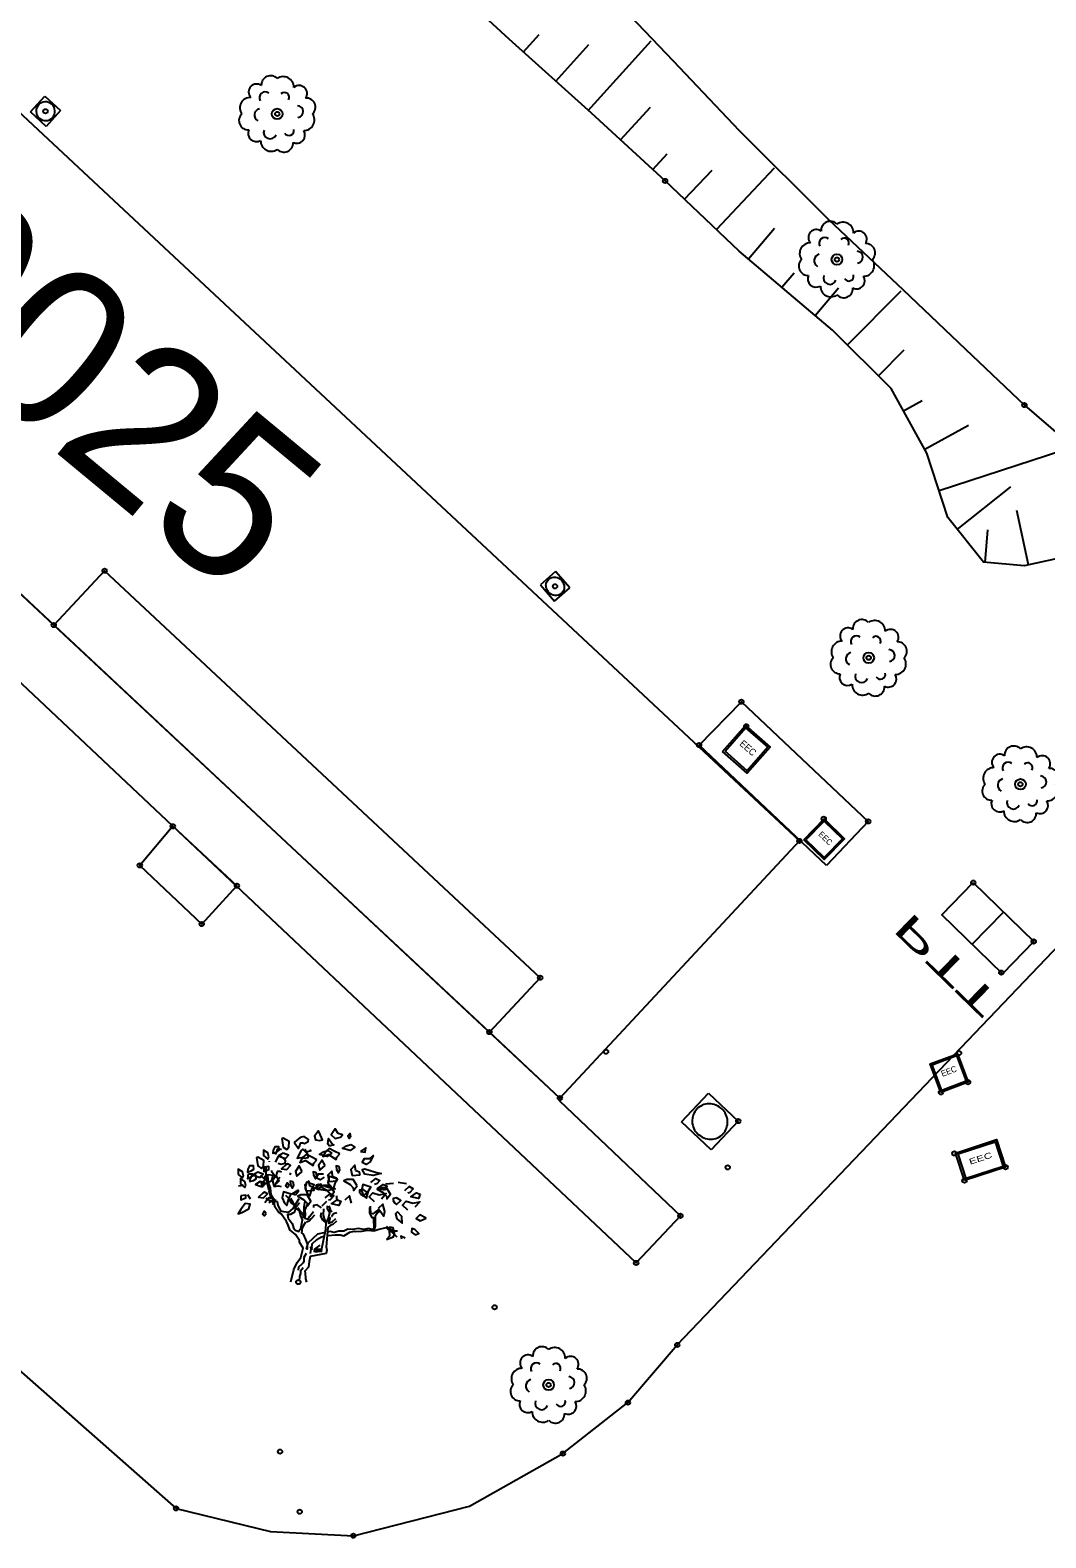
# Model space of a CAD drawing. Extents: x 344013 to 344423, y 298505 to 298795.
# Drawn here: x 344153.42 to 344176.66, y 298671.56 to 298706.06 of the extents above; entities that cross this region are included whole.
import ezdxf

# ---------------------------------------------------------------- set-up
doc = ezdxf.new("R2010")
doc.units = 0
for name, color, linetype in [('Default', 7, 'Continuous'), ('DH_CADRE -CARTOUCHE', 7, 'Continuous'), ('DH_CADRE-CARTOUCHE-NORD', 7, 'Continuous'), ('GO MUR EXTERIEUR', 7, 'Continuous'), ('PC_CONCRETE', 7, 'Continuous'), ('PS_BOLT', 7, 'Continuous'), ('PS_CONST', 7, 'Continuous'), ('PS_HIDDEN', 7, 'Continuous'), ('RES_ELECTRICITE', 7, 'Continuous'), ('TOPO_POINT', 7, 'Continuous'), ('TOPO_TALUS-TERRAIN NATUREL', 7, 'Continuous'), ('VOIRIE_BORDURE', 7, 'Continuous'), ('VOIRIE_ESPACE VERT', 7, 'Continuous')]:
    doc.layers.add(name, color=color, linetype=linetype)

# ---------------------------------------------------------------- blocks, each defined once
blk = doc.blocks.new('CT2')
at = {"layer": 'Default'}
blk.add_lwpolyline([(0, 0), (1, 0), (1, 1), (0, 1)], close=True, dxfattribs=at)
blk.add_lwpolyline([(0.5, 1), (0.5, 0)], dxfattribs=at)
blk.add_text('PTT', height=0.6, dxfattribs=at).set_placement((-0.3, 1.425))
blk = doc.blocks.new('REG_INC')
at = {"layer": 'Default'}
for p, q in [((0, 1), (1, 1)), ((0, 0), (0, 1)), ((1, 1), (1, 0)), ((1, 0), (0, 0))]:
    blk.add_line(p, q, dxfattribs=at)
for centre, start, end in [((0.498, 0.5), 135.0055, 180.0055), ((0.5, 0.498), 90.0058, 135.0058), ((0.5, 0.5), 45.0069, 90.0069), ((0.499, 0.499), 0.0066, 45.0066), ((0.501, 0.5), 180.0066, 225.0066), ((0.501, 0.499), 315.0055, 0.0055), ((0.499, 0.498), 225.0069, 270.0069), ((0.499, 0.5), 270.0058, 315.0058)]:
    blk.add_arc(centre, 0.44, start, end, dxfattribs=at)
blk = doc.blocks.new('RES_ELECTRICITE')
at = {"layer": 'RES_ELECTRICITE'}
for points in [[(0, 0), (0, 1), (1, 1), (1, 0)], [(0.05, 0.05), (0.05, 0.95), (0.95, 0.95), (0.95, 0.05)]]:
    blk.add_lwpolyline(points, close=True, dxfattribs=at)
blk.add_text('EEC', height=0.2, dxfattribs=at).set_placement((0.237, 0.46))
blk = doc.blocks.new('POINT_DISPLAY')
at = {"layer": 'Default'}
blk.add_circle((0, 0), 0.05, dxfattribs=at)
blk = doc.blocks.new('ARB1')
at = {"layer": 'Default'}
blk.add_circle((0, 0), 0.122, dxfattribs=at)
for centre, radius, start, end in [((-0.153, 0.664), 0.211, 43.6925, 183.5969), ((0.139, 0.613), 0.241, 358.4583, 125.1928), ((-0.613, 0.139), 0.241, 88.4583, 215.1928), ((-0.471, 0.503), 0.183, 53.9554, 222.2066), ((-0.276, 0.37), 0.134, 52.4396, 209.5496), ((0.164, 0.38), 0.112, 330.5895, 133.7127), ((0.501, 0.468), 0.183, 325.1444, 131.0175), ((0.664, 0.153), 0.211, 313.6925, 93.5969), ((-0.373, -0.024), 0.149, 103.7092, 242.3465), ((0.458, 0.052), 0.137, 276.6214, 88.967), ((0.613, -0.139), 0.241, 268.4583, 35.1928), ((-0.664, -0.153), 0.211, 133.6925, 273.5969), ((-0.478, -0.443), 0.19, 155.2243, 300.9377), ((-0.139, -0.613), 0.241, 178.4583, 305.1928), ((-0.163, -0.42), 0.148, 159.5371, 338.1663), ((0.153, -0.664), 0.211, 223.6925, 3.5969), ((0.271, -0.38), 0.112, 210.5895, 13.7127), ((0.448, -0.483), 0.188, 243.1323, 33.0297)]:
    blk.add_arc(centre, radius, start, end, dxfattribs=at)
blk = doc.blocks.new('FLAMBOY')
at = {"layer": 'Default'}
for p, q in [((-0.832, 3.464), (-0.832, 3.442)), ((-0.238, 3.069), (-0.213, 3.132)), ((-1.57, 2.764), (-1.707, 2.742)), ((2.497, 2.813), (2.722, 2.832)), ((3.097, 2.813), (2.859, 2.854)), ((-1.371, 2.378), (-1.446, 2.497)), ((0.808, 2.303), (0.671, 2.171)), ((0.866, 1.688), (0.866, 1.688)), ((0.407, 0.927), (0.337, 1.011))]:
    blk.add_line(p, q, dxfattribs=at)
for points in [[(0.617, 4.053), (0.692, 4.072), (0.592, 4.288), (0.579, 4.328), (0.467, 4.172), (0.492, 4.072)], [(1.054, 4.113), (1.204, 4.15), (1.267, 4.213), (1.142, 4.25), (1.054, 4.388), (0.942, 4.213)], [(-0.471, 4.106), (-0.433, 3.866), (-0.333, 3.791), (-0.271, 3.866), (-0.258, 4.025), (-0.433, 4.122)], [(0.054, 4.141), (-0.108, 4.006), (-0.108, 3.985), (0.004, 3.825), (0.042, 3.906), (0.067, 3.985), (0.129, 3.985), (0.179, 3.966), (0.279, 4.025), (0.292, 4.085), (0.167, 4.163)], [(0.892, 3.891), (0.867, 3.95), (0.842, 3.95), (0.867, 4.106), (0.979, 3.95), (1.017, 3.928)], [(1.504, 3.938), (1.617, 3.863), (1.479, 3.763), (1.267, 3.822), (1.379, 3.9)], [(1.504, 4.15), (1.479, 4.25), (1.417, 4.172), (1.454, 4.113)], [(-1.195, 3.564), (-1.157, 3.324), (-1.057, 3.249), (-0.995, 3.324), (-0.982, 3.483), (-1.157, 3.58)], [(-0.846, 3.581), (-0.871, 3.697), (-0.996, 3.775), (-0.996, 3.622), (-0.871, 3.522)], [(-0.621, 3.722), (-0.546, 3.772), (-0.558, 3.872), (-0.671, 3.872), (-0.721, 3.772), (-0.733, 3.691)], [(-0.433, 3.691), (-0.571, 3.61), (-0.408, 3.55), (-0.358, 3.55), (-0.283, 3.631)], [(0.292, 3.644), (0.254, 3.685), (0.129, 3.803), (0.079, 3.763), (-0.008, 3.606), (-0.033, 3.547), (0.079, 3.569), (0.167, 3.547), (0.279, 3.569)], [(0.533, 3.5), (0.371, 3.581), (0.221, 3.656), (0.121, 3.562), (0.046, 3.421), (0.208, 3.481), (0.421, 3.34), (0.446, 3.403)], [(0.767, 3.338), (0.679, 3.494), (0.579, 3.338), (0.617, 3.2)], [(0.958, 3.693), (0.821, 3.593), (0.608, 3.653), (0.721, 3.731), (0.846, 3.768)], [(1.192, 3.669), (1.029, 3.75), (0.879, 3.825), (0.779, 3.731), (0.704, 3.591), (0.867, 3.65), (1.079, 3.51), (1.104, 3.572)], [(1.779, 3.738), (1.917, 3.716), (1.929, 3.838)], [(1.829, 3.422), (1.892, 3.541), (2.042, 3.541), (2.142, 3.622), (2.054, 3.441), (1.942, 3.366)], [(-1.72, 3.08), (-1.595, 2.98), (-1.57, 3.039), (-1.595, 3.155), (-1.72, 3.233)], [(-1.345, 3.18), (-1.27, 3.23), (-1.282, 3.33), (-1.395, 3.33), (-1.445, 3.23), (-1.457, 3.149)], [(-1.421, 3.103), (-1.308, 3.103), (-1.296, 3.038), (-1.446, 2.953)], [(-1.392, 2.878), (-1.279, 2.909), (-1.204, 2.959), (-1.217, 3.059), (-1.329, 3.059), (-1.379, 2.959)], [(-1.132, 3.008), (-1.082, 3.008), (-1.007, 3.089), (-1.157, 3.149), (-1.295, 3.067)], [(-0.958, 2.81), (-0.758, 2.906), (-0.721, 3.047), (-0.858, 3.066), (-0.983, 2.888), (-1.058, 2.772)], [(-0.983, 3.285), (-0.983, 3.166), (-0.846, 3.225), (-0.846, 3.306)], [(-0.7, 2.76), (-0.55, 2.897), (-0.638, 3.053), (-0.738, 2.897)], [(-0.308, 3.388), (-0.358, 3.36), (-0.483, 3.241), (-0.333, 3.225), (-0.221, 3.341)], [(0.108, 3.168), (0.021, 3.325), (-0.079, 3.168), (-0.042, 3.031)], [(0.508, 3.137), (0.421, 3.156), (0.433, 3.056), (0.496, 2.956), (0.533, 3.037)], [(1.108, 2.9), (1.096, 2.978), (0.983, 3.015), (0.958, 3.175), (0.846, 3.056), (0.883, 2.881)], [(1.117, 2.953), (1.054, 2.853), (0.992, 2.638), (0.917, 2.697), (0.854, 2.853), (0.892, 3.028)], [(1.167, 3.306), (1.079, 3.325), (1.092, 3.225), (1.154, 3.125), (1.192, 3.206)], [(1.767, 3.069), (1.754, 3.147), (1.642, 3.185), (1.617, 3.344), (1.504, 3.225), (1.542, 3.05)], [(1.829, 3.225), (1.904, 3.244), (2.204, 3.147), (2.367, 3.106), (2.142, 3.05), (1.904, 3.091)], [(-1.504, 2.768), (-1.529, 2.884), (-1.654, 2.962), (-1.654, 2.809), (-1.529, 2.709)], [(-1.092, 2.878), (-1.229, 2.796), (-1.067, 2.737), (-1.017, 2.737), (-0.942, 2.818)], [(-0.258, 2.775), (-0.321, 2.841), (-0.371, 2.756), (-0.321, 2.706)], [(-0.15, 2.866), (-0.238, 2.885), (-0.225, 2.785), (-0.163, 2.685), (-0.125, 2.766)], [(-0.079, 2.484), (-0.179, 2.525), (-0.004, 2.631), (-0.004, 2.584)], [(0.3, 2.903), (0.187, 2.785), (0.225, 2.61), (0.45, 2.628), (0.437, 2.707), (0.325, 2.744)], [(0.396, 2.684), (0.458, 2.784), (0.233, 2.859), (0.196, 2.684), (0.258, 2.528), (0.333, 2.468)], [(0.579, 2.653), (0.654, 2.753), (0.654, 2.8), (0.479, 2.694)], [(0.512, 2.785), (0.587, 2.803), (0.887, 2.707), (1.05, 2.666), (0.825, 2.61), (0.587, 2.65)], [(0.733, 2.768), (0.646, 2.728), (0.821, 2.628), (0.908, 2.531), (0.921, 2.453), (1.021, 2.587), (0.908, 2.768)], [(1.679, 2.756), (1.567, 2.938), (1.392, 2.938), (1.304, 2.897), (1.479, 2.797), (1.567, 2.7), (1.579, 2.622)], [(1.804, 2.497), (1.854, 2.46), (1.979, 2.569), (1.854, 2.653), (1.754, 2.635), (1.754, 2.575)], [(2.009, 2.616), (2.072, 2.716), (1.847, 2.791), (1.809, 2.616), (1.872, 2.46), (1.947, 2.4)], [(2.522, 2.7), (2.347, 2.7), (2.259, 2.66), (2.434, 2.56), (2.522, 2.463), (2.534, 2.385), (2.634, 2.519)], [(2.479, 2.635), (2.267, 2.678), (2.429, 2.794), (2.529, 2.753)], [(-1.617, 1.996), (-1.417, 2.093), (-1.379, 2.234), (-1.517, 2.253), (-1.642, 2.074), (-1.717, 1.959)], [(-1.642, 2.471), (-1.642, 2.353), (-1.504, 2.412), (-1.504, 2.493)], [(-0.967, 2.574), (-1.017, 2.546), (-1.142, 2.428), (-0.992, 2.412), (-0.879, 2.528)], [(-0.263, 2.413), (-0.2, 2.513), (-0.425, 2.588), (-0.463, 2.413), (-0.4, 2.257), (-0.325, 2.197)], [(0.075, 2.497), (-0.013, 2.457), (0.162, 2.357), (0.25, 2.26), (0.262, 2.182), (0.362, 2.316), (0.25, 2.497)], [(1.112, 2.353), (1.212, 2.313), (1.162, 2.194), (0.95, 2.238)], [(2.284, 2.104), (2.359, 2.007), (2.447, 1.888), (2.472, 2.025), (2.422, 2.235)], [(2.759, 2.26), (2.809, 2.222), (2.934, 2.332), (2.809, 2.416), (2.709, 2.397), (2.709, 2.338)], [(3.484, 2.516), (3.434, 2.397), (3.222, 2.441), (3.384, 2.557)], [(-0.917, 1.962), (-0.979, 2.028), (-1.029, 1.943), (-0.979, 1.893)], [(2.834, 2.01), (2.784, 1.957), (2.822, 1.813), (2.972, 1.688), (2.959, 1.882)], [(3.659, 1.835), (3.472, 1.925), (3.372, 1.819), (3.484, 1.75)], [(2.522, 1.216), (2.722, 1.294), (2.747, 1.394), (2.709, 1.55), (2.622, 1.569), (2.597, 1.491), (2.609, 1.316)], [(3.334, 1.51), (3.247, 1.532), (3.234, 1.432), (3.347, 1.354), (3.447, 1.394)]]:
    blk.add_lwpolyline(points, close=True, dxfattribs=at)
for points in [[(-0.579, 3.4), (-0.492, 3.378), (-0.379, 3.4), (-0.367, 3.475), (-0.404, 3.515), (-0.529, 3.634), (-0.579, 3.593), (-0.667, 3.437)], [(-0.654, 3.656), (-0.617, 3.737), (-0.592, 3.815), (-0.529, 3.815), (-0.479, 3.796)], [(0.321, 3.781), (0.358, 3.759), (0.233, 3.721), (0.208, 3.781), (0.183, 3.781)], [(-1.092, 3.053), (-0.992, 2.978), (-0.929, 3.053)], [(-0.719, 2.357), (-0.785, 2.441), (-0.834, 2.61), (-0.916, 2.965), (-0.916, 3.15), (-0.916, 3.302)], [(-0.883, 3.049), (-0.867, 2.846), (-0.801, 2.694), (-0.785, 2.509), (-0.686, 2.323), (-0.604, 2.306), (-0.588, 2.205), (-0.506, 2.036), (-0.424, 2.019), (-0.276, 2.002), (-0.145, 2.103), (-0.079, 2.221), (0.02, 2.39)], [(-0.767, 3.193), (-0.767, 3.171), (-0.654, 3.012), (-0.617, 3.093), (-0.592, 3.171), (-0.529, 3.171), (-0.479, 3.153)], [(0.737, 3), (0.625, 2.925), (0.512, 2.982), (0.575, 3.1), (0.725, 3.1)], [(-0.945, 2.799), (-1.032, 2.846), (-1.082, 2.817)], [(-0.529, 2.99), (-0.579, 2.949), (-0.667, 2.793), (-0.692, 2.734), (-0.579, 2.756), (-0.492, 2.734)], [(2.079, 2.85), (2.217, 2.969), (2.329, 2.91), (2.242, 2.81), (2.179, 2.794)], [(3.134, 2.557), (3.197, 2.572), (3.284, 2.672), (3.172, 2.732), (3.034, 2.613)], [(-0.846, 2.281), (-0.683, 2.363), (-0.846, 2.413), (-0.958, 2.266)], [(-0.21, 0.009), (-0.128, 0.364), (-0.03, 0.566), (0.069, 0.701), (0.134, 0.972), (0.036, 1.141), (0.036, 1.191), (-0.079, 1.36), (-0.243, 1.495), (-0.292, 1.63), (-0.341, 1.732), (-0.489, 1.951), (-0.571, 2.002), (-0.67, 2.154), (-0.686, 2.255), (-0.932, 2.39)], [(-0.663, 2.36), (-0.663, 2.313), (-0.738, 2.213)], [(-0.112, 2.188), (-0.194, 2.255), (-0.276, 2.39), (-0.358, 2.475)], [(0.036, 2.272), (-0.079, 2.12), (-0.112, 2.002), (-0.227, 1.934), (-0.309, 1.934), (-0.292, 1.833), (-0.177, 1.681), (-0.128, 1.529), (-0.095, 1.495), (0.003, 1.445), (0.069, 1.546), (0.085, 1.58), (0.118, 1.782), (0.069, 1.901), (0.036, 2.036), (-0.062, 2.103)], [(-0.227, 2.407), (-0.161, 2.289), (-0.095, 2.205)], [(-0.013, 2.137), (0.085, 2.002), (0.151, 1.901), (0.151, 1.85), (0.167, 2.002), (0.167, 2.154), (0.2, 2.323)], [(0.249, 2.221), (0.184, 2.069), (0.2, 1.934), (0.184, 1.833), (0.282, 1.799), (0.331, 1.884), (0.43, 2.019)], [(0.662, 2.128), (0.537, 2.213), (0.437, 2.194), (0.437, 2.135)], [(0.725, 2.099), (0.713, 1.918), (0.76, 1.761), (0.819, 1.724), (0.866, 1.833), (0.901, 1.99), (0.83, 2.099), (0.83, 2.184)], [(0.862, 2.353), (0.925, 2.369), (1.012, 2.469), (0.9, 2.528), (0.762, 2.41)], [(0.877, 2.184), (0.912, 2.075), (0.959, 2.015)], [(1.096, 2.465), (1.096, 2.406), (1.146, 2.328)], [(1.517, 2.263), (1.467, 2.472), (1.329, 2.341)], [(2.179, 2.3), (2.029, 2.438), (2.129, 2.553), (2.317, 2.497), (2.517, 2.535), (2.379, 2.378)], [(2.298, 2.063), (2.193, 1.99), (2.134, 1.954), (2.087, 1.966), (2.063, 2.075), (2.063, 2.172)], [(3.134, 2.063), (2.984, 2.2), (3.084, 2.316), (3.272, 2.26), (3.472, 2.297), (3.334, 2.141)], [(1.089, 1.749), (0.983, 1.652), (0.912, 1.616), (0.842, 1.567), (0.795, 1.011), (0.819, 0.915), (0.795, 0.818), (0.337, 0.733), (0.313, 0.588), (0.29, 0.431), (0.184, 0.31), (0.196, 0.274), (0.208, 0.093), (0.231, -0.001)], [(0.463, 1.917), (0.364, 1.816), (0.315, 1.749), (0.233, 1.715)], [(0.619, 1.06), (0.466, 0.939), (0.454, 0.878), (0.666, 0.915), (0.783, 1.519), (0.795, 1.688), (0.701, 1.773), (0.642, 1.894), (0.666, 1.99)], [(2.04, 2.135), (2.04, 1.978), (2.099, 1.845), (2.146, 1.845), (2.146, 1.712), (2.157, 1.628), (2.157, 1.543), (2.122, 1.507), (2.005, 1.531), (1.876, 1.507), (1.723, 1.531), (1.547, 1.507), (1.418, 1.519), (1.3, 1.459), (1.159, 1.459), (1.03, 1.422), (0.912, 1.446), (0.819, 1.434)], [(0.912, 1.857), (0.866, 1.688), (0.971, 1.724), (1.077, 1.821)], [(0.948, 1.882), (1.006, 1.966), (1.1, 1.99)], [(2.169, 1.483), (2.204, 1.604), (2.204, 1.797), (2.204, 1.906), (2.263, 1.99), (2.345, 2.039)], [(0.208, 1.712), (0.114, 1.555), (0.09, 1.41), (0.137, 1.374), (0.208, 1.217), (0.255, 1.096), (0.255, 0.939), (0.231, 0.951), (0.278, 1.12), (0.56, 1.386), (0.736, 1.422)], [(0.384, 0.975), (0.396, 1.096), (0.525, 1.217), (0.666, 1.301), (0.736, 1.314)], [(0.854, 1.338), (1.053, 1.35), (1.194, 1.35), (1.3, 1.326), (1.476, 1.434), (1.594, 1.459), (1.629, 1.446), (1.817, 1.459), (1.981, 1.483), (2.157, 1.471), (2.275, 1.507), (2.51, 1.567), (2.557, 1.519), (2.733, 1.386), (2.815, 1.301)], [(2.51, 1.592), (2.721, 1.459), (2.768, 1.471), (2.803, 1.471), (2.839, 1.471)], [(3.059, 1.257), (2.934, 1.316), (2.947, 1.235)], [(0.349, 0.818), (0.372, 0.939), (0.396, 1.011)], [(0.49, 0.866), (0.619, 0.891), (0.678, 0.891)], [(0.501, 0.939), (0.607, 0.939), (0.689, 0.939)], [(0.22, 0.818), (0.161, 0.709), (0.161, 0.6), (0.137, 0.552), (0.102, 0.516), (0.008, 0.431), (-0.004, 0.347)], [(0.137, 0.407), (0.067, 0.31), (0.067, 0.25), (0.032, 0.165), (0.02, 0.032)]]:
    blk.add_lwpolyline(points, dxfattribs=at)

msp = doc.modelspace()

# ---------------------------------------------------------------- linework, layer by layer
at = {"layer": 'DH_CADRE -CARTOUCHE'}
msp.add_lwpolyline([(344163.929, 298683.13), (344165.092, 298684.375), (344155.123, 298693.692), (344153.96, 298692.447), (344140.184, 298705.334), (344145.624, 298711.233), (344171.024, 298687.508), (344165.544, 298681.621)], close=True, dxfattribs=at)
at = {"layer": 'GO MUR EXTERIEUR'}
msp.add_lwpolyline([(344145.624, 298711.233), (344171.024, 298687.508), (344165.544, 298681.621), (344140.184, 298705.334)], close=True, dxfattribs=at)
at = {"layer": 'PS_BOLT'}
msp.add_lwpolyline([(344165.544, 298681.621), (344165.531, 298681.558), (344168.3, 298678.926), (344167.289, 298677.848), (344153.365, 298690.972), (344139.141, 298704.253), (344140.184, 298705.334)], dxfattribs=at)
for points in [[(344171.646, 298686.945), (344168.73, 298689.7), (344169.697, 298690.692), (344172.598, 298687.952)], [(344156.685, 298687.841), (344155.93, 298686.947), (344157.346, 298685.603), (344158.152, 298686.481)]]:
    msp.add_lwpolyline(points, close=True, dxfattribs=at)
at = {"layer": 'PS_HIDDEN'}
msp.add_lwpolyline([(344163.929, 298683.13), (344153.96, 298692.447)], dxfattribs=at)
at = {"layer": 'TOPO_TALUS-TERRAIN NATUREL'}
for p, q in [((344164.709, 298705.569), (344165.067, 298705.966)), ((344165.452, 298704.899), (344166.207, 298705.736)), ((344166.194, 298704.228), (344167.63, 298705.819)), ((344166.931, 298703.552), (344167.62, 298704.301)), ((344167.668, 298702.875), (344167.995, 298703.231)), ((344168.398, 298702.192), (344169.029, 298702.858)), ((344169.124, 298701.504), (344170.456, 298702.91)), ((344169.86, 298700.827), (344170.455, 298701.528)), ((344170.623, 298700.18), (344170.905, 298700.513)), ((344171.385, 298699.533), (344171.922, 298700.165)), ((344172.123, 298698.858), (344173.356, 298700.101)), ((344172.833, 298698.154), (344173.419, 298698.744)), ((344173.41, 298697.349), (344173.837, 298697.584)), ((344173.893, 298696.473), (344174.893, 298697.024)), ((344174.22, 298695.529), (344177.051, 298696.448)), ((344174.638, 298694.637), (344175.866, 298695.615)), ((344176.27, 298693.827), (344176.001, 298695.073)), ((344175.276, 298693.882), (344175.34, 298694.624))]:
    msp.add_line(p, q, dxfattribs=at)
for points in [[(344148.445, 298717.676), (344150.54, 298719.466), (344152.414, 298719.731), (344154.52, 298718.736), (344157.154, 298716.789), (344159.618, 298714.441), (344161.857, 298712.179), (344163.938, 298709.792), (344165.996, 298707.602), (344168.133, 298705.364), (344169.649, 298703.764), (344171.689, 298701.731), (344173.402, 298700.124), (344174.981, 298698.62), (344176.175, 298697.484), (344177.055, 298696.727), (344177.983, 298696.033), (344178.792, 298695.819), (344179.816, 298696.274), (344181.06, 298697.498), (344181.167, 298697.785)], [(344192.371, 298706.767), (344190.985, 298705.261), (344189.552, 298703.768), (344187.895, 298701.96), (344186.776, 298700.516), (344185.144, 298698.764), (344183.988, 298697.846), (344182.522, 298696.699), (344181.424, 298695.135), (344180.359, 298693.822), (344179.336, 298693.603), (344178.417, 298693.99), (344177.213, 298694.032), (344176.166, 298693.805), (344175.237, 298693.885), (344174.421, 298694.91), (344173.943, 298696.382), (344173.127, 298697.863), (344171.784, 298699.194), (344169.649, 298701.006), (344167.952, 298702.614), (344166.263, 298704.166), (344164.386, 298705.861), (344162.327, 298707.753)]]:
    msp.add_lwpolyline(points, dxfattribs=at)
at = {"layer": 'VOIRIE_BORDURE'}
msp.add_lwpolyline([(344128.542, 298697.099), (344156.76, 298672.229), (344158.923, 298671.699), (344160.816, 298671.605), (344163.478, 298672.279), (344165.611, 298673.484), (344167.1, 298674.65), (344168.229, 298675.97), (344185.426, 298693.989), (344196.039, 298705.71), (344211.949, 298722.43)], dxfattribs=at)

# ---------------------------------------------------------------- block references
at = {"layer": 'DH_CADRE-CARTOUCHE-NORD', "xscale": 1.932152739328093, "yscale": -1.029208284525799, "rotation": -44.24922000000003}
msp.add_blockref('CT2', (344175.003, 298686.554), dxfattribs=at)
at = {"layer": 'PC_CONCRETE'}
for p, xscale, yscale, rotation in [((344153.753, 298704.554), 0.48813467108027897, 0.491645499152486, -132.20937000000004), ((344165.77, 298693.299), 0.46057142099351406, -0.49462206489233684, -138.83616000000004), ((344169.626, 298681.093), 0.935414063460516, 0.9050997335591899, 136.74329999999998)]:
    msp.add_blockref('REG_INC', p, dxfattribs=dict(at, xscale=xscale, yscale=yscale, rotation=rotation))
at = {"layer": 'RES_ELECTRICITE'}
for p, xscale, yscale, rotation in [((344169.268, 298689.555), 0.7507731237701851, 0.7890939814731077, -41.21122458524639), ((344171.124, 298687.531), 0.649637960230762, 0.666145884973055, -44.13421264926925), ((344174.263, 298681.752), 0.6634214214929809, 0.695493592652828, 20.56731581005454), ((344174.803, 298679.732), 0.99024213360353, 0.661972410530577, 18.125818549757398)]:
    msp.add_blockref('RES_ELECTRICITE', p, dxfattribs=dict(at, xscale=xscale, yscale=yscale, rotation=rotation))
at = {"layer": 'TOPO_POINT'}
for p in [(344153.771, 298704.208), (344159.074, 298704.146), (344167.952, 298702.614), (344171.884, 298700.814), (344176.175, 298697.484), (344155.123, 298693.692), (344165.434, 298693.334), (344153.96, 298692.447), (344172.61, 298691.698), (344169.697, 298690.692), (344169.808, 298690.131), (344168.73, 298689.7), (344176.083, 298688.804), (344171.583, 298688.013), (344156.685, 298687.841), (344172.598, 298687.952), (344171.024, 298687.508), (344155.93, 298686.947), (344158.152, 298686.481), (344175.003, 298686.554), (344157.346, 298685.603), (344176.387, 298685.205), (344165.092, 298684.375), (344175.645, 298684.492), (344163.929, 298683.13), (344166.599, 298682.682), (344174.678, 298682.65), (344174.885, 298681.985), (344165.544, 298681.621), (344174.263, 298681.752), (344169.626, 298681.093), (344169.384, 298680.035), (344174.573, 298680.353), (344175.744, 298680.04), (344174.803, 298679.732), (344168.3, 298678.926), (344167.289, 298677.848), (344159.557, 298677.408), (344164.048, 298676.834), (344168.229, 298675.97), (344165.286, 298675.056), (344167.1, 298674.65), (344159.14, 298673.53), (344165.611, 298673.484), (344156.76, 298672.229), (344159.59, 298672.154), (344160.816, 298671.605)]:
    msp.add_blockref('POINT_DISPLAY', p, dxfattribs=at)
at = {"layer": 'VOIRIE_ESPACE VERT'}
for p in [(344159.074, 298704.146), (344171.884, 298700.814), (344172.61, 298691.698), (344176.083, 298688.804), (344165.286, 298675.056)]:
    msp.add_blockref('ARB1', p, dxfattribs=at)
at = {"layer": 'VOIRIE_ESPACE VERT', "xscale": 0.8, "yscale": 0.8000000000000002}
msp.add_blockref('FLAMBOY', (344159.557, 298677.408), dxfattribs=at)

# ---------------------------------------------------------------- texts
at = {"layer": 'PS_CONST'}
msp.add_text('0025', height=3.662, rotation=320.3665, dxfattribs=at).set_placement((344149.662, 298699.997))

doc.saveas('drawing.dxf')
